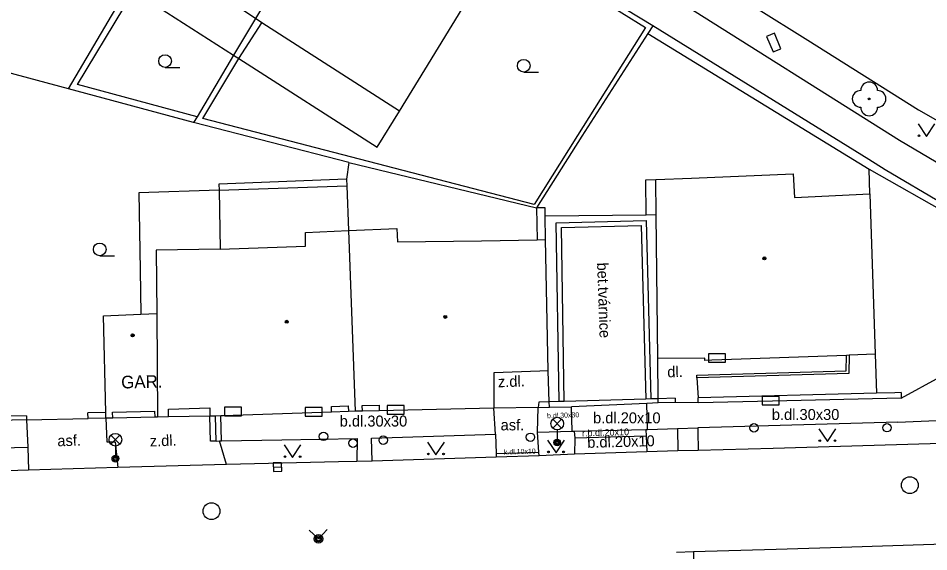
# Model space of a CAD drawing. Extents: x -595546 to -593986, y -1160845 to -1159202.
# Drawn here: x -595028.2 to -594974.1, y -1160780.5 to -1160748.8 of the extents above; entities that cross this region are included whole.
import ezdxf

# ---------------------------------------------------------------- set-up
doc = ezdxf.new("R2010")
doc.units = 0
for name, color, linetype in [('DOP - kresba z DSPS bez souradnic', 7, 'Continuous'), ('DOP - rozhrani ploch obecne', 7, 'Continuous'), ('Level 22', 7, 'Continuous'), ('Level 24', 7, 'Continuous'), ('Level 27', 7, 'Continuous'), ('Level 28', 7, 'Continuous'), ('Level 31', 7, 'Continuous'), ('Level 33', 7, 'Continuous'), ('Level 36', 7, 'Continuous'), ('Level 39', 7, 'Continuous'), ('TM - budovy zdene_ betonove - NP', 7, 'Continuous'), ('TM - budovy zdene_ betonove - VP', 7, 'Continuous'), ('TM - chodniky - VP', 7, 'Continuous'), ('TM - komunikace - VP', 7, 'Continuous'), ('TM - letecke snimky - pomocna linie', 7, 'Continuous'), ('TM - plot drateny_ kovovy - VP', 7, 'Continuous'), ('TM - plot zdeny_ ohradni zed - VP', 7, 'Continuous'), ('TM - podezdivka plotu - VP', 7, 'Continuous'), ('TM - popis objektu', 7, 'Continuous'), ('TM - popis povrchu', 7, 'Continuous'), ('TM - rozhrani mezi zpev. plochami mezi sebou - VP', 7, 'Continuous'), ('TM - rozhrani ploch obecne - VP', 7, 'Continuous'), ('TM - schody - VP', 7, 'Continuous'), ('TM - vjezd na pozemek', 7, 'Continuous'), ('TM - zed operna - VP', 7, 'Continuous')]:
    doc.layers.add(name, color=color, linetype=linetype)

msp = doc.modelspace()

# ---------------------------------------------------------------- linework, layer by layer
at = {"layer": 'DOP - kresba z DSPS bez souradnic'}
for points in [[(-595025.19, -1160752.95), (-595022.17, -1160747.83)], [(-595020.34, -1160747.78), (-595015.38, -1160750.95)], [(-595024.65, -1160752.69), (-595021.9, -1160748.13)], [(-595015.07, -1160751.15), (-595013.7, -1160749.02)], [(-595017.21, -1160754.71), (-595015.07, -1160751.15)], [(-595017.55, -1160754.62), (-595024.65, -1160752.69)], [(-594997.52, -1160759.82), (-595017.21, -1160754.71)], [(-595016.24, -1160758.97), (-595008.66, -1160758.71)]]:
    msp.add_lwpolyline(points, dxfattribs=at)
at = {"layer": 'DOP - rozhrani ploch obecne'}
for points in [[(-595014.08, -1160748.77), (-595015.38, -1160750.95)], [(-595015.38, -1160750.95), (-595017.55, -1160754.62)], [(-595015.38, -1160750.95), (-595015.07, -1160751.15)], [(-595015.07, -1160751.15), (-595006.85, -1160756.41)], [(-595025.19, -1160752.95), (-595030.73, -1160751.46)], [(-595017.76, -1160754.95), (-595025.19, -1160752.95)], [(-595006.85, -1160756.41), (-595005.52, -1160754.27)], [(-595017.55, -1160754.62), (-595017.76, -1160754.95)], [(-595008.53, -1160757.33), (-595017.76, -1160754.95)], [(-595008.53, -1160757.33), (-595008.67, -1160758.32)], [(-595008.53, -1160757.33), (-594997.38, -1160760.03)], [(-595008.67, -1160758.32), (-595016.25, -1160758.61)], [(-595016.25, -1160758.61), (-595016.24, -1160758.97)], [(-595008.67, -1160758.32), (-595008.66, -1160758.71)], [(-595008.66, -1160758.71), (-595008.56, -1160761.38)], [(-595016.24, -1160758.97), (-595016.18, -1160762.48)]]:
    msp.add_lwpolyline(points, dxfattribs=at)
at = {"layer": 'Level 22'}
msp.add_circle((-594977.63, -1160753.55), 0.05, dxfattribs=at)
for centre, start, end in [((-594977.63, -1160753.05), 0, 180), ((-594978.13, -1160753.55), 90, 270), ((-594977.13, -1160753.55), 270, 90), ((-594977.63, -1160754.05), 180, 0)]:
    msp.add_arc(centre, 0.5, start, end, dxfattribs=at)
at = {"layer": 'Level 24'}
for points in [[(-594983.719, -1160749.838), (-594983.328, -1160750.759), (-594982.868, -1160750.564), (-594983.258, -1160749.643)], [(-594987.167, -1160769.208), (-594986.167, -1160769.208), (-594986.167, -1160768.708), (-594987.167, -1160768.708)], [(-594983.978, -1160771.739), (-594982.978, -1160771.739), (-594982.978, -1160771.239), (-594983.978, -1160771.239)], [(-595006.258, -1160772.289), (-595005.258, -1160772.289), (-595005.258, -1160771.789), (-595006.258, -1160771.789)], [(-595015.917, -1160772.388), (-595014.917, -1160772.388), (-595014.917, -1160771.888), (-595015.917, -1160771.888)], [(-595011.128, -1160772.409), (-595010.128, -1160772.409), (-595010.128, -1160771.909), (-595011.128, -1160771.909)]]:
    msp.add_lwpolyline(points, close=True, dxfattribs=at)
at = {"layer": 'Level 27'}
msp.add_line((-595013.02, -1160775.447), (-595012.52, -1160775.433), dxfattribs=at)
msp.add_lwpolyline([(-595013.013, -1160775.697), (-595012.513, -1160775.683), (-595012.527, -1160775.183), (-595013.027, -1160775.197)], close=True, dxfattribs=at)
for centre in [(-594975.21, -1160776.52), (-595016.69, -1160778.06)]:
    msp.add_circle(centre, 0.5, dxfattribs=at)
at = {"layer": 'Level 28'}
for centre in [(-594984.47, -1160773.11), (-594976.57, -1160773.1), (-595010.04, -1160773.62), (-594997.75, -1160773.67), (-595008.29, -1160774.02), (-595006.49, -1160773.84)]:
    msp.add_circle(centre, 0.25, dxfattribs=at)
at = {"layer": 'Level 31'}
msp.add_lwpolyline([(-595009.831, -1160779.16), (-595010.34, -1160779.71), (-595010.89, -1160779.201)], dxfattribs=at)
for radius in [0.25, 0.18, 0.11]:
    msp.add_circle((-595010.34, -1160779.71), radius, dxfattribs=at)
at = {"layer": 'Level 33'}
for p, q in [((-594996.425, -1160773.12), (-594995.895, -1160772.59)), ((-594996.425, -1160772.59), (-594995.895, -1160773.12)), ((-594996.16, -1160773.23), (-594996.16, -1160773.98)), ((-595022.665, -1160774.08), (-595022.135, -1160773.55)), ((-595022.665, -1160773.55), (-595022.135, -1160774.08)), ((-595022.4, -1160774.19), (-595022.4, -1160774.94))]:
    msp.add_line(p, q, dxfattribs=at)
for centre, radius in [((-594996.16, -1160772.855), 0.375), ((-595022.4, -1160773.815), 0.375), ((-594996.16, -1160773.98), 0.2), ((-594996.16, -1160773.98), 0.145), ((-594996.16, -1160773.98), 0.0876), ((-595022.4, -1160774.94), 0.2), ((-595022.4, -1160774.94), 0.145), ((-595022.4, -1160774.94), 0.0876)]:
    msp.add_circle(centre, radius, dxfattribs=at)
at = {"layer": 'Level 36'}
for p, q in [((-595019.45, -1160751.675), (-595018.575, -1160751.675)), ((-594998.15, -1160751.955), (-594997.275, -1160751.955)), ((-595023.33, -1160762.875), (-595022.455, -1160762.875))]:
    msp.add_line(p, q, dxfattribs=at)
for points in [[(-594974.72, -1160755.04), (-594974.22, -1160755.79), (-594973.72, -1160755.04)], [(-594980.61, -1160773.17), (-594980.11, -1160773.92), (-594979.61, -1160773.17)], [(-595003.86, -1160773.96), (-595003.36, -1160774.71), (-595002.86, -1160773.96)], [(-594996.73, -1160773.84), (-594996.23, -1160774.59), (-594995.73, -1160773.84)], [(-595012.38, -1160774.12), (-595011.88, -1160774.87), (-595011.38, -1160774.12)]]:
    msp.add_lwpolyline(points, dxfattribs=at)
for centre, radius in [((-595019.45, -1160751.3), 0.375), ((-594998.15, -1160751.58), 0.375), ((-594974.67, -1160755.74), 0.05), ((-595023.33, -1160762.5), 0.375), ((-594980.56, -1160773.87), 0.05), ((-594979.661, -1160773.87), 0.05), ((-594996.68, -1160774.54), 0.05), ((-594995.781, -1160774.54), 0.05), ((-595012.33, -1160774.82), 0.05), ((-595011.431, -1160774.82), 0.05), ((-595003.81, -1160774.66), 0.05), ((-595002.911, -1160774.66), 0.05)]:
    msp.add_circle(centre, radius, dxfattribs=at)
at = {"layer": 'Level 39'}
for centre, radius in [((-594983.85, -1160763.03), 0.09), ((-594983.85, -1160763.03), 0.0398), ((-595002.81, -1160766.51), 0.09), ((-595012.22, -1160766.8), 0.09), ((-595012.22, -1160766.8), 0.0398), ((-595002.81, -1160766.51), 0.0398), ((-595021.38, -1160767.61), 0.09), ((-595021.38, -1160767.61), 0.0398)]:
    msp.add_circle(centre, radius, dxfattribs=at)
at = {"layer": 'TM - budovy zdene_ betonove - NP'}
for points in [[(-595009.56, -1160772.17), (-595009.57, -1160771.83), (-595008.57, -1160771.8), (-595008.56, -1160772.13)], [(-595007.73, -1160772.11), (-595007.74, -1160771.78), (-595006.74, -1160771.76), (-595006.73, -1160772.09)], [(-595022.56, -1160772.53), (-595022.57, -1160772.17), (-595020.07, -1160772.11), (-595020.06, -1160772.48)], [(-595019.24, -1160772.46), (-595019.25, -1160771.99), (-595016.8, -1160771.92), (-595016.79, -1160772.42)]]:
    msp.add_lwpolyline(points, dxfattribs=at)
at = {"layer": 'TM - budovy zdene_ betonove - VP'}
for points in [[(-595007.78, -1160738.22), (-595014.08, -1160748.77)], [(-595004.03, -1160751.82), (-594999.15, -1160743.83)], [(-595014.08, -1160748.77), (-595020.28, -1160744.65)], [(-595013.7, -1160749.02), (-595014.08, -1160748.77)], [(-595005.52, -1160754.27), (-595013.7, -1160749.02)], [(-595005.52, -1160754.27), (-595004.03, -1160751.82)], [(-594990.3, -1160758.35), (-594988.19, -1160758.26)], [(-594988.19, -1160758.26), (-594982.14, -1160758.01)], [(-594982.14, -1160758.01), (-594982.07, -1160759.42)], [(-594990.28, -1160760.45), (-594990.3, -1160758.35)], [(-594982.07, -1160759.42), (-594977.59, -1160759.2)], [(-594977.59, -1160759.2), (-594977.28, -1160768.73)], [(-594990.19, -1160768.99), (-594990.28, -1160760.45)], [(-595011.12, -1160761.49), (-595008.56, -1160761.38)], [(-595011.12, -1160762.3), (-595011.12, -1160761.49)], [(-595008.56, -1160761.38), (-595005.69, -1160761.26)], [(-595008.56, -1160761.38), (-595008.17, -1160772.12)], [(-595005.69, -1160761.26), (-595005.65, -1160762.05)], [(-595005.65, -1160762.05), (-595000.65, -1160761.99)], [(-595000.65, -1160761.99), (-594997.34, -1160761.92)], [(-594997.34, -1160761.92), (-594996.85, -1160761.91)], [(-594996.69, -1160769.71), (-594996.85, -1160761.91)], [(-595016.18, -1160762.48), (-595011.12, -1160762.3)], [(-595023.1, -1160766.44), (-595020.9, -1160766.35)], [(-595020.9, -1160766.35), (-595019.95, -1160766.31)], [(-595022.98, -1160772.19), (-595023.1, -1160766.44)], [(-594987.39, -1160768.96), (-594990.19, -1160768.99)], [(-594978.97, -1160768.8), (-594986.38, -1160769.07), (-594986.98, -1160769.09), (-594987.39, -1160769.11)], [(-594987.39, -1160769.11), (-594987.39, -1160768.96)], [(-594978.82, -1160768.79), (-594978.97, -1160768.8)], [(-594977.28, -1160768.73), (-594978.82, -1160768.79)], [(-594997.19, -1160769.73), (-594999.93, -1160769.83)], [(-594999.93, -1160769.83), (-594999.92, -1160771.94)], [(-594996.69, -1160769.71), (-594997.19, -1160769.73)], [(-595022.97, -1160772.54), (-595022.98, -1160772.19)], [(-595009.56, -1160772.17), (-595015.98, -1160772.4)], [(-595008.56, -1160772.13), (-595009.56, -1160772.17)], [(-595008.17, -1160772.12), (-595008.56, -1160772.13)], [(-595007.73, -1160772.11), (-595008.17, -1160772.12)], [(-595006.73, -1160772.09), (-595007.73, -1160772.11)], [(-594999.92, -1160771.94), (-595006.73, -1160772.09)], [(-595022.56, -1160772.53), (-595022.97, -1160772.54)], [(-595020.06, -1160772.48), (-595022.56, -1160772.53)], [(-595019.9, -1160772.48), (-595020.06, -1160772.48)], [(-595019.24, -1160772.46), (-595019.9, -1160772.48)], [(-595016.79, -1160772.42), (-595019.24, -1160772.46)], [(-595016.13, -1160772.4), (-595016.46, -1160772.41), (-595016.79, -1160772.42)], [(-595015.98, -1160772.4), (-595016.13, -1160772.4)]]:
    msp.add_lwpolyline(points, dxfattribs=at)
at = {"layer": 'TM - chodniky - VP'}
for points in [[(-594975.82, -1160756.03), (-594989.04, -1160747.7)], [(-594971.58, -1160758.54), (-594975.82, -1160756.03)], [(-594975.92, -1160772.77), (-594969.5, -1160772.5), (-594954.16, -1160772.09)], [(-595027.68, -1160772.64), (-595024.02, -1160772.56)], [(-594975.92, -1160772.77), (-594987.81, -1160773.1)], [(-594997.33, -1160773.36), (-594995.27, -1160773.31)], [(-594997.25, -1160774.56), (-594997.33, -1160773.36)], [(-594995.27, -1160773.31), (-594995.15, -1160773.31)], [(-594995.15, -1160773.31), (-594995.11, -1160773.73)], [(-594990.89, -1160773.2), (-594990.8, -1160773.2)], [(-594990.89, -1160773.2), (-594990.88, -1160773.61)], [(-594990.8, -1160773.2), (-594989.01, -1160773.14)], [(-594989.01, -1160773.14), (-594988.99, -1160774.48)], [(-594987.81, -1160773.1), (-594987.81, -1160773.3), (-594987.79, -1160774.45)], [(-595015.81, -1160775.28), (-595016.21, -1160773.88)], [(-595016.21, -1160773.88), (-595016.09, -1160773.88)], [(-595016.09, -1160773.88), (-595012.51, -1160773.82), (-595008.05, -1160773.74)], [(-595008.05, -1160773.74), (-595008.06, -1160775.11)], [(-595007.16, -1160775.09), (-595007.19, -1160773.72), (-594999.83, -1160773.48)], [(-594999.83, -1160773.48), (-594999.79, -1160774.64)], [(-594995.11, -1160773.73), (-594995.14, -1160774.67)], [(-594990.88, -1160773.61), (-594990.84, -1160774.53)], [(-595037.16, -1160774.49), (-595027.61, -1160774.26)], [(-595027.61, -1160774.26), (-595027.57, -1160775.63)], [(-594999.79, -1160774.64), (-594999.78, -1160774.85)], [(-594997.24, -1160774.77), (-594997.25, -1160774.56)], [(-594988.06, -1160780.46), (-594988.07, -1160781.79), (-594980.11, -1160781.56)]]:
    msp.add_lwpolyline(points, dxfattribs=at)
at = {"layer": 'TM - komunikace - VP'}
for points in [[(-594987.49, -1160746.15), (-594981.28, -1160750.05)], [(-594981.28, -1160750.05), (-594974.7, -1160754.2)], [(-594974.7, -1160754.2), (-594969.26, -1160757.32)], [(-594972, -1160774), (-594983.33, -1160774.33), (-594987.79, -1160774.45)], [(-594990.84, -1160774.53), (-594995.14, -1160774.67)], [(-594988.99, -1160774.48), (-594990.84, -1160774.53)], [(-594987.79, -1160774.45), (-594988.99, -1160774.48)], [(-594999.78, -1160774.85), (-595007.16, -1160775.09)], [(-594997.24, -1160774.77), (-594999.78, -1160774.85)], [(-594995.14, -1160774.67), (-594997.24, -1160774.77)], [(-595022.26, -1160775.47), (-595027.57, -1160775.63)], [(-595015.81, -1160775.28), (-595022.26, -1160775.47)], [(-595008.06, -1160775.11), (-595009.16, -1160775.13), (-595015.81, -1160775.28)], [(-595007.16, -1160775.09), (-595008.06, -1160775.11)], [(-595027.57, -1160775.63), (-595037.08, -1160775.92)], [(-594979.27, -1160780.21), (-594966.49, -1160779.79)], [(-594989.07, -1160780.5), (-594988.06, -1160780.46)], [(-594988.06, -1160780.46), (-594983.15, -1160780.32), (-594979.27, -1160780.21)]]:
    msp.add_lwpolyline(points, dxfattribs=at)
at = {"layer": 'TM - letecke snimky - pomocna linie'}
for points in [[(-595016.24, -1160758.97), (-595021.02, -1160759.13), (-595020.94, -1160763.71)], [(-594990.87, -1160760.46), (-594996.87, -1160760.52)], [(-595016.18, -1160762.48), (-595019.98, -1160762.55), (-595019.95, -1160766.31)], [(-595020.94, -1160763.71), (-595020.9, -1160766.35)], [(-595019.95, -1160766.31), (-595019.9, -1160772.48)], [(-594977.28, -1160768.73), (-594977.2, -1160771.05)]]:
    msp.add_lwpolyline(points, dxfattribs=at)
at = {"layer": 'TM - plot drateny_ kovovy - VP'}
for points in [[(-594997.95, -1160744.93), (-594990.91, -1160749.3)], [(-594990.91, -1160749.3), (-594994.95, -1160755.72)], [(-594990.78, -1160749.67), (-594977.63, -1160757.73)], [(-594994.95, -1160755.72), (-594997.52, -1160759.82)], [(-594977.63, -1160757.73), (-594972.74, -1160760.51), (-594972.44, -1160760.91)], [(-594996.63, -1160771.57), (-594996.69, -1160769.71)], [(-594975.73, -1160771.35), (-594973.42, -1160770.08)], [(-594977.2, -1160771.05), (-594987.79, -1160771.32)], [(-594976.11, -1160771.02), (-594977.2, -1160771.05)], [(-594975.72, -1160771), (-594976.11, -1160771.02)], [(-594996.63, -1160771.57), (-594997.25, -1160771.59)], [(-594996.04, -1160771.55), (-594996.63, -1160771.57)], [(-594995.74, -1160771.54), (-594996.04, -1160771.55)], [(-594990.89, -1160771.4), (-594995.74, -1160771.54)], [(-594990.59, -1160771.39), (-594990.89, -1160771.4)], [(-594990.16, -1160771.38), (-594990.59, -1160771.39)], [(-594989.16, -1160771.35), (-594990.16, -1160771.38)], [(-595022.98, -1160772.19), (-595024.03, -1160772.21)], [(-595027.68, -1160772.4), (-595030, -1160772.44)]]:
    msp.add_lwpolyline(points, dxfattribs=at)
at = {"layer": 'TM - plot zdeny_ ohradni zed - VP'}
msp.add_lwpolyline([(-594997.38, -1160760.03), (-594997.34, -1160761.92)], dxfattribs=at)
at = {"layer": 'TM - podezdivka plotu - VP'}
for points in [[(-594990.48, -1160749.21), (-594997.84, -1160744.72)], [(-594990.48, -1160749.21), (-594990.78, -1160749.67)], [(-594977.65, -1160757.15), (-594990.48, -1160749.21)], [(-594990.78, -1160749.67), (-594994.7, -1160755.77)], [(-594994.7, -1160755.77), (-594997.38, -1160760.03)], [(-594976.67, -1160757.76), (-594977.65, -1160757.15)], [(-594973.26, -1160759.78), (-594976.67, -1160757.76)], [(-594996.88, -1160760.02), (-594997.38, -1160760.03)], [(-594996.87, -1160760.52), (-594996.88, -1160760.02)], [(-594996.85, -1160761.91), (-594996.87, -1160760.52)], [(-594995.74, -1160771.54), (-594995.91, -1160761.2), (-594991.17, -1160761.08), (-594990.89, -1160771.4)], [(-594975.72, -1160771), (-594975.73, -1160771.35)], [(-594997.25, -1160771.59), (-594997.29, -1160771.9)], [(-594996.62, -1160771.88), (-594996.63, -1160771.57)], [(-594990.84, -1160771.66), (-594995.32, -1160771.85)], [(-594990.16, -1160771.63), (-594990.84, -1160771.66)], [(-594989.15, -1160771.6), (-594990.16, -1160771.63)], [(-594989.16, -1160771.35), (-594989.15, -1160771.6)], [(-594987.78, -1160771.62), (-594987.79, -1160771.32)], [(-594975.73, -1160771.35), (-594983.38, -1160771.53), (-594987.78, -1160771.62)], [(-595024.02, -1160772.56), (-595024.03, -1160772.21)], [(-595027.68, -1160772.64), (-595030.25, -1160772.7)], [(-595027.68, -1160772.4), (-595027.68, -1160772.64)], [(-595022.97, -1160772.54), (-595024.02, -1160772.56)]]:
    msp.add_lwpolyline(points, dxfattribs=at)
at = {"layer": 'TM - rozhrani mezi zpev. plochami mezi sebou - VP'}
for points in [[(-594990.8, -1160773.2), (-594990.84, -1160771.66)], [(-594999.83, -1160773.48), (-594999.92, -1160771.94)], [(-594997.33, -1160773.36), (-594997.29, -1160771.9)], [(-594995.27, -1160773.31), (-594995.32, -1160771.85)], [(-595027.68, -1160772.64), (-595027.61, -1160774.26)], [(-595022.97, -1160772.54), (-595022.91, -1160773.94), (-595022.41, -1160773.95), (-595022.26, -1160775.47)], [(-594995.15, -1160773.31), (-594990.89, -1160773.2)], [(-594989.01, -1160773.14), (-594987.81, -1160773.1)], [(-594990.88, -1160773.61), (-594995.11, -1160773.73)], [(-594999.79, -1160774.64), (-594997.25, -1160774.56)]]:
    msp.add_lwpolyline(points, dxfattribs=at)
at = {"layer": 'TM - rozhrani ploch obecne - VP'}
for points in [[(-594977.59, -1160759.2), (-594977.63, -1160757.73)], [(-594990.9, -1160758.37), (-594990.3, -1160758.35)], [(-594990.87, -1160760.46), (-594990.9, -1160758.37)], [(-594990.28, -1160760.45), (-594990.87, -1160760.46)], [(-594990.16, -1160771.38), (-594990.19, -1160768.99)], [(-594978.82, -1160768.79), (-594978.84, -1160769.87), (-594987.86, -1160770.13)], [(-594987.86, -1160770.13), (-594987.86, -1160769.98), (-594978.99, -1160769.72), (-594978.97, -1160768.8)], [(-594987.86, -1160770.13), (-594987.79, -1160771.32)], [(-594990.16, -1160771.63), (-594990.16, -1160771.38)], [(-594997.29, -1160771.9), (-594996.62, -1160771.88)], [(-594996.62, -1160771.88), (-594995.32, -1160771.85)], [(-595016.42, -1160773.9), (-595016.75, -1160773.91), (-595016.79, -1160772.42)], [(-595016.09, -1160773.88), (-595016.13, -1160772.4)], [(-595016.42, -1160773.9), (-595016.21, -1160773.88)]]:
    msp.add_lwpolyline(points, dxfattribs=at)
at = {"layer": 'TM - schody - VP'}
msp.add_lwpolyline([(-595016.42, -1160773.9), (-595016.46, -1160772.41)], dxfattribs=at)
at = {"layer": 'TM - vjezd na pozemek'}
for points in [[(-594987.78, -1160771.62), (-594989.15, -1160771.6)], [(-594997.29, -1160771.9), (-594999.92, -1160771.94)]]:
    msp.add_lwpolyline(points, dxfattribs=at)
at = {"layer": 'TM - zed operna - VP'}
msp.add_lwpolyline([(-594996.04, -1160771.55), (-594996.22, -1160760.91), (-594990.88, -1160760.77), (-594990.59, -1160771.39)], dxfattribs=at)

# ---------------------------------------------------------------- texts
at = {"layer": 'TM - popis objektu'}
msp.add_text('GAR.', height=0.75, rotation=1.28, dxfattribs=at).set_placement((-595022.05, -1160770.77))
at = {"layer": 'TM - popis povrchu'}
for s, height, rotation, p in [('bet.tvárnice', 0.65, 271.9572, (-594993.79, -1160763.29)), ('dl.', 0.65, 1.9572, (-594989.61, -1160770.11)), ('z.dl.', 0.65, 1.9572, (-594999.67, -1160770.7)), ('b.dl.30x30', 0.3, 1.9572, (-594996.76, -1160772.54)), ('r.b.dl.20x10', 0.4, 1.6098, (-594994.68, -1160773.62)), ('asf.', 0.65, 1.9572, (-595025.84, -1160774.21)), ('z.dl.', 0.65, 1.9572, (-595020.35, -1160774.22)), ('b.dl.20x10', 0.65, 1.4791, (-594994.37, -1160774.3)), ('k.dl.10x10', 0.3, 1.8476, (-594999.32, -1160774.7))]:
    msp.add_text(s, height=height, rotation=rotation, dxfattribs=at).set_placement(p)
for s, p in [('b.dl.30x30', (-595009.08, -1160773.03)), ('b.dl.20x10', (-594994.03, -1160772.84)), ('b.dl.30x30', (-594983.41, -1160772.64)), ('asf.', (-594999.52, -1160773.26))]:
    msp.add_text(s, height=0.65, dxfattribs=at).set_placement(p)

doc.saveas('drawing.dxf')
